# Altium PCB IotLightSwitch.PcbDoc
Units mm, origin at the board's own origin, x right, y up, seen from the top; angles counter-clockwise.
Board outline 68.2 x 35.18 mm, 2 copper layers (Top Layer, Bottom Layer), stack 1.586 mm thick; 15 components, 13 nets, 48 pads, 4 vias.
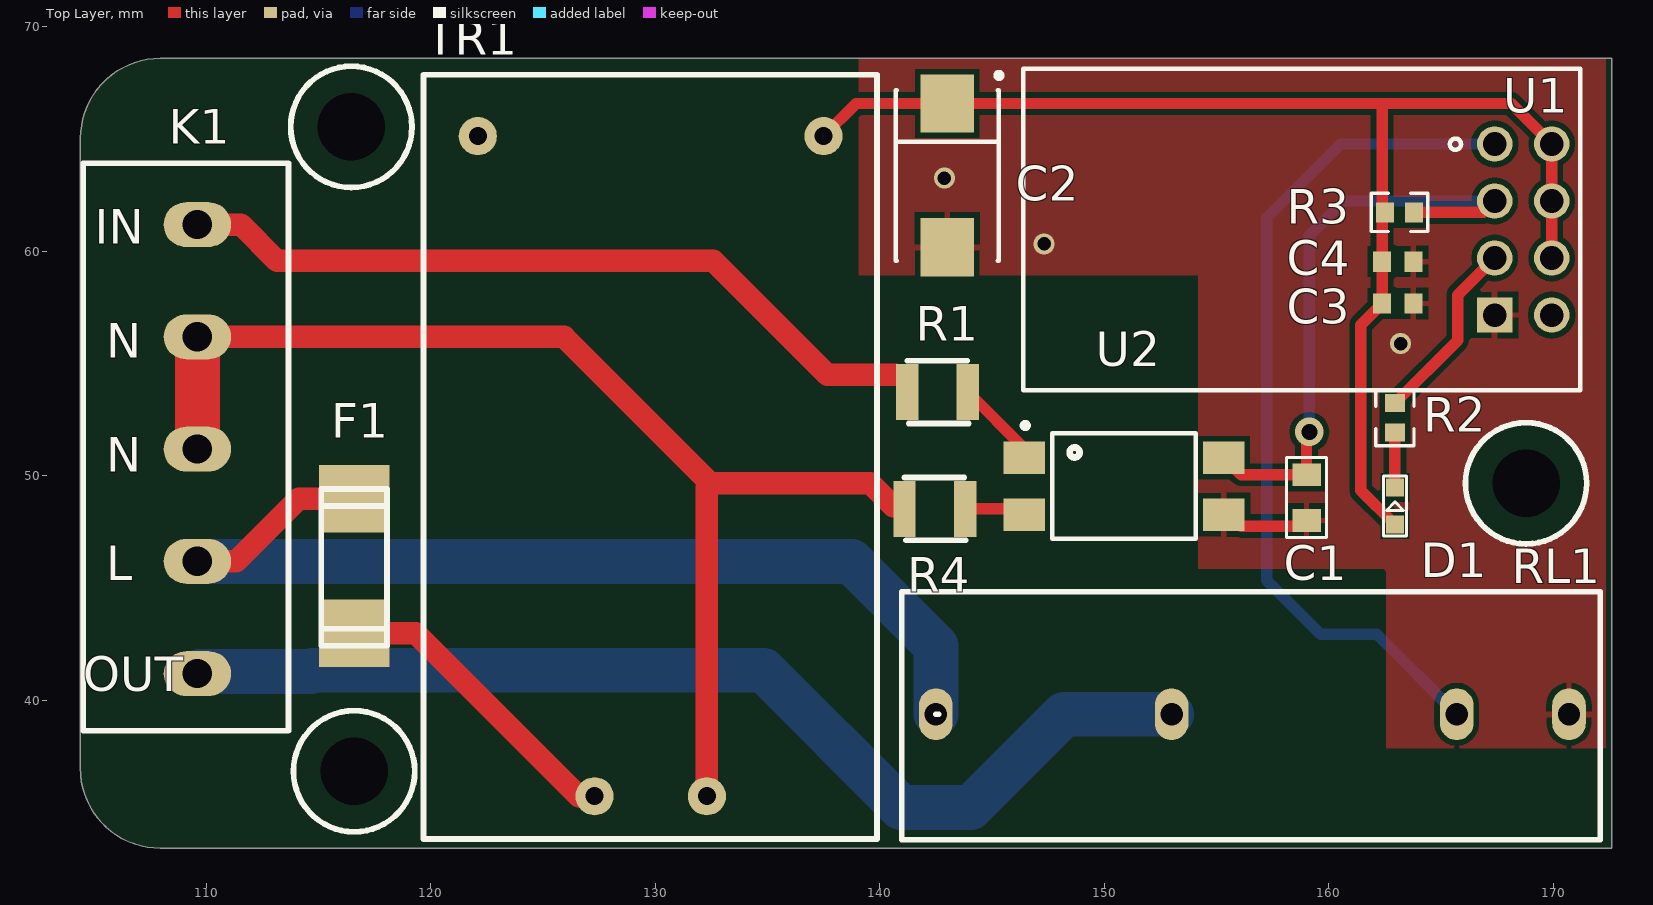
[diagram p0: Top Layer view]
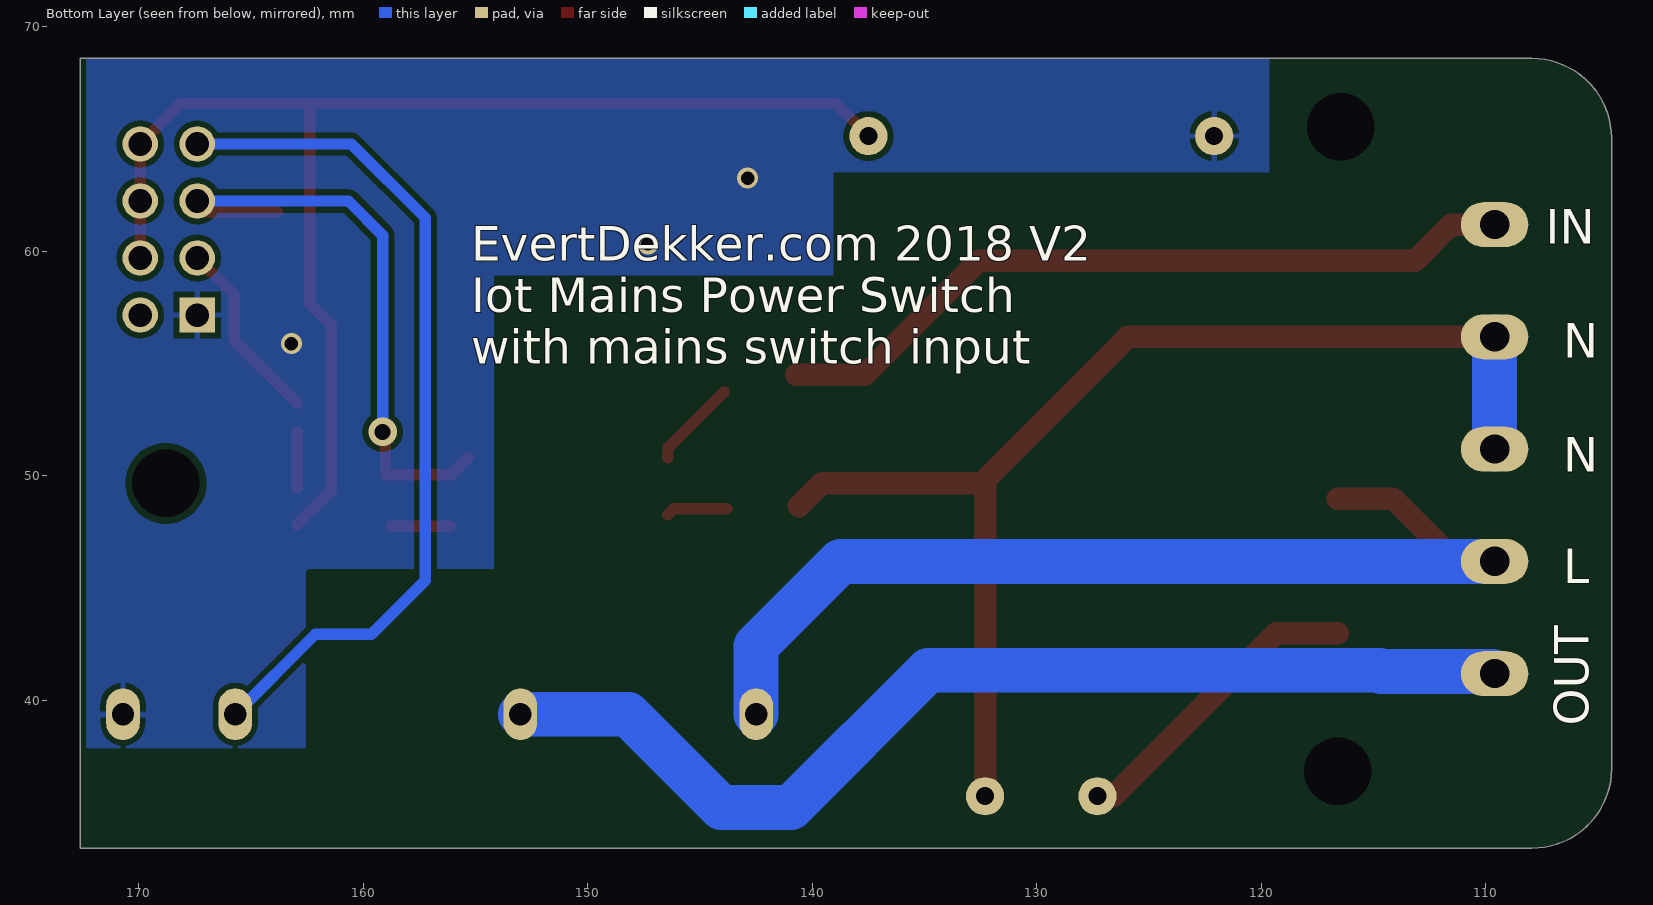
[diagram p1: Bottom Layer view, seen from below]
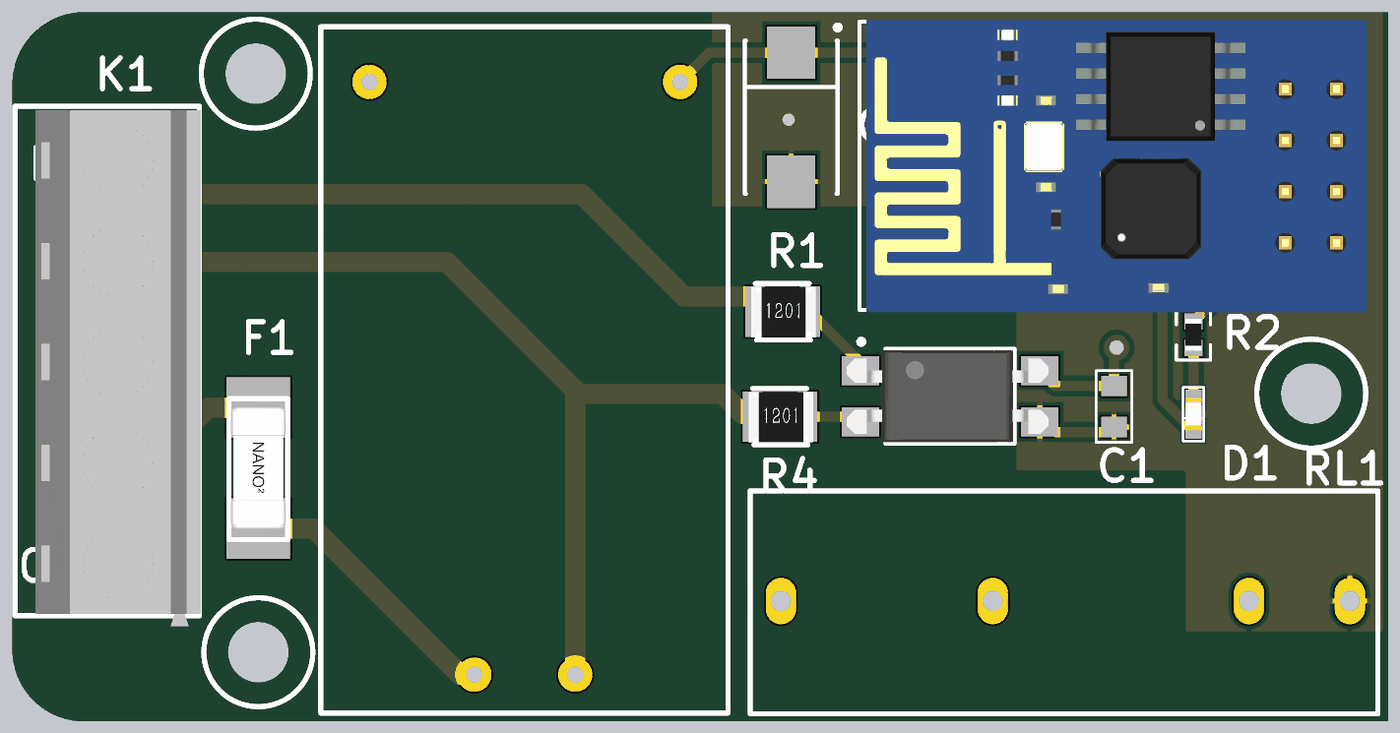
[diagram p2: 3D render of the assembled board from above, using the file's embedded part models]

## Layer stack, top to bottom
Top Solder: solder mask 0.0102, Solder Resist, Dk 3.5
Top Layer: signal copper 0.018
Dielectric1: core 1.55, FR-4, Dk 4.8
Bottom Layer: signal copper 0.018
Bottom Solder: solder mask 0.0102, Solder Resist, Dk 3.5

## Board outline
104.392,36.959 ccw(c107.95,36.959) 107.95,33.401 172.593,33.401 172.593,68.58 107.95,68.58 107.952,68.582 ccw(c107.952,65.024) 104.394,65.024

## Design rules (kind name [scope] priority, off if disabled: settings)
Clearance "Schematic Clearance Constraint" [InNetClass('Undefined')] p1: gap=2
Clearance [All] p2: gap=0.254
PolygonConnect PolygonConnect_1 [IsVia AND InNet('GND')] p1: connectstyle=Direct reliefconductorwidth=0.254 reliefentries=4 polygonreliefangle="90 Angle" airgapwidth=0.254
PolygonConnect [All] p2: connectstyle=Relief reliefconductorwidth=0.254 reliefentries=4 polygonreliefangle="90 Angle" airgapwidth=0.254
RoutingVias [All] p1: holewidth=0.711 width=1.27 viastyle="Through Hole" minholewidth=0.711 minwidth=1.27 maxholewidth=0.711 maxwidth=1.27
SolderMaskExpansion [All] p1: expansion=0.102
Width "Schematic Width Constraint" [InNetClass('Undefined')] p1: maxlimit=3 minlimit=1 preferedwidth=2 minimp=50.000000 maximp=50.000000 favimp=50.000000
Width [All] p2: maxlimit=0.508 minlimit=0.254 preferedwidth=0.305 minimp=50.000000 maximp=50.000000 favimp=50.000000
30 further rules are at their usual default settings.

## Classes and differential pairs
net class Undefined: IN L N NetF1_2 OUT

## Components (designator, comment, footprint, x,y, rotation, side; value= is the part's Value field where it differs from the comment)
C1 "10uF" 0805C-GENERIC 159.004,49.784 r270 top
C2 "T491X" X 143.002,63.373 r270 top
C3 "Cap Semi" 1608[0603] 163.068,57.658 r180 top
C4 "Cap Semi" 1608[0603] 163.068,59.527 r180 top
D1 "Led" LED1608 162.941,48.641 r90 top
F1 "Fuse" SmdFuse1808 116.586,45.974 r270 top
K1 "ScrewTerminal5x5.00mm" ScrewTerminal5x5.00 109.601,51.181 r90 top
R1 "Resistor" RES1210 141.224,53.721 r0 top
R2 "Resistor" RES0603R 162.941,52.578 r90 top
R3 "Resistor" RES0603R 163.144,61.722 r0 top
R4 "Resistor" RES1210 141.097,48.514 r0 top
RL1 "SSR-SAI4002D" SAI4002D 142.494,39.37 r0 top
TR1 "HLK-PM03" HLK-PM03 129.794,50.419 r90 top
U1 "ESP8266-01/ESP-01" XCVR_ESP8266-01/ESP-01 167.386,60.96 r180 top
U2 "SFH6286-3T" SOIC254P977X460-4N 150.876,49.53 r0 top

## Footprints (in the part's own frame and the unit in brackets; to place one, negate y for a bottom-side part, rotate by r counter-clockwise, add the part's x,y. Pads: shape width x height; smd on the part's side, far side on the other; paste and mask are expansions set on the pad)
0805C-GENERIC [mil] "CAPACITOR 0805"
  rect 40x50 smd: 1(-10,0) 2(70,0)
  silkscreen extent -40,-35 100,35, body extent -11,-25 70,25, height 26
1608[0603] [mm] "Chip Capacitor, Body 1.6x0.8mm, IPC High Density"
  rect 0.8x0.9 smd: 1(-0.7,0) 2(0.7,0)
  body extent -0.87,-0.48 0.87,0.48, height 1.3
HLK-PM03 [mm] "Hi-Link HLK-PM03 Power Module"
  round 1.7 hole 0.8: 1(-14.7,2.5) 2(-14.7,-2.5) 3(14.7,7.7) 4(14.7,-7.7)
  silkscreen extent -16.6,-10.08 17.43,10.12, body extent -16.6,-10.07 17.43,10.12, height 15
LED1608 [mm] "1608"
  rect 0.8x0.8 smd: A(-0.826,0) K(0.826,0)
  silkscreen extent -1.33,-0.51 1.33,0.51, body extent -0.8,-0.4 0.8,0.4, height 1.11
RES0603R [mm] "resistor 0603 reflow soldering"
  rect 0.8x0.9 smd: 1(-0.65,0) 2(0.65,0)
  silkscreen extent -1.25,-0.85 1.25,0.85, body extent -0.8,-0.4 0.8,0.4, height 0.45
RES1210 [mm] "RES1210"
  rect 1x2.5 smd: 1(0,0) 2(2.7,0)
  silkscreen extent 0,-1.4 2.73,1.4, body extent -0.2,-1.27 3,1.23, height 0.53
SAI4002D [mm] "SAI4002D Solid State Relay"
  oval 1.5x2.3 hole 1: 1(0,0) 2(10.5,0) 3(23.2,0) 4(28.2,0)
  silkscreen extent -1.52,-5.59 29.59,5.46
ScrewTerminal5x5.00 [mm] "Screw terminal 5p 5.00mm"
  oval 2x3 hole 1.3: 1(-10,0) 2(-5,0) 3(0,0) 4(5,0) 5(10,0)
  silkscreen extent -12.54,-4.06 12.73,5.08, body extent -13.05,-4.14 12.55,4.06, height 10
SmdFuse1808 [mm] "Smd Fuse 1808 Hand Solder"
  rect 3x3.15 smd: 1(-3,0) 2(3,0)
  silkscreen extent -3.43,-1.46 3.56,1.46, body extent -3.05,-1.35 3.05,1.35, height 2.7
SOIC254P977X460-4N [mm]
  rect 1.85x1.45 smd: 1(-4.45,1.27) 2(-4.45,-1.27) 3(4.45,-1.27) 4(4.45,1.27)
  silkscreen extent -4.5,-2.35 3.2,2.8, body extent -5.13,-2.29 4.87,2.29, height 3.86
X [mm] "Capacitor, SM Tantalum; Body 7.3 x 4.3 mm (LxW typ)"
  rect 2.6x2.4 smd: 1(-3.2,0) 2(3.2,0)
  silkscreen extent -4.57,-2.3 3.8,2.43
XCVR_ESP8266-01/ESP-01 [mm]
  rect 1.575x1.575 hole 1.05: 1(0,3.81)
  round 1.575 hole 1.05: 2(-2.54,3.81) 3(0,1.27) 4(-2.54,1.27) 5(0,-1.27) 6(-2.54,-1.27) 7(0,-3.81) 8(-2.54,-3.81)
  silkscreen extent -3.81,-7.15 21,7.15, body extent -4.14,-7.24 20.65,7.26, height 5.88

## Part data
C1: library part 0805C-10UF-16V-X5R-TDK, "CAPACITOR 0805 CERAMIC"
C2: "Solid Tantalum Chip Capacitor, Standard T491 Series - Industrial Grade"
C3 C4: "Capacitor (Semiconductor SIM Model)"
TR1: "Hi-Link HLK-PM03 3.3VDC/3W Power Module"
U2: "SFH6286 Series 5300 Vrms 55 V Phototransistor Output Optocoupler - SMD-4"

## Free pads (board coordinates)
  oval 1.5x2.3 hole 3 unplated: 0(116.459,65.532) 0(116.586,36.83) 0(168.783,49.657)

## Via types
v1: diameter 0.935, hole 0.6, Top Layer to Bottom Layer, 3 vias
v2: diameter 1.27, hole 0.711, Top Layer to Bottom Layer, 1 vias

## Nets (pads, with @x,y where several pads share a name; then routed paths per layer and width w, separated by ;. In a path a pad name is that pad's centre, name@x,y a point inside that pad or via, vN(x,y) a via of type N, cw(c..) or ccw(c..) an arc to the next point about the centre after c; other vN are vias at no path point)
GND: C1.2 C2.2 C3.1 C4.1 RL1.4 TR1.3 U1.1 U2.3 | length 2.7
  Top Layer w0.508: U2.3@156.084,47.752 C1.2@158.75,47.752
  other v1: 163.195,55.88 147.32,60.325 142.875,63.246
IN: K1.5 R1.1 | length 33.9
  Top Layer w1: K1.5 111.539,61.181 113.157,59.563 132.588,59.563 137.668,54.483 140.716,54.483
L: F1.1 K1.2 RL1.1 | length 45.6
  Top Layer w1: K1.2 111.332,46.181 114.125,48.974 F1.1
  Bottom Layer w2: K1.2 138.731,46.181 142.494,42.418 RL1.1
N: K1.3 K1.4 R4.1 TR1.2 | length 57.9
  Top Layer w1: K1.4 125.937,56.181 132.461,49.657 139.573,49.657 140.589,48.641 ; TR1.2 132.294,49.49
  Top Layer w2: K1.3 K1.4
  Bottom Layer w2: K1.3 K1.4
NetC1_1: C1.1 R3.2 U1.5 U2.4 | length 27.4
  Top Layer w0.508: U2.4 156.088,50.038 C1.1 159.004,51.816 v2(159.131,51.943) ; R3.2 166.878,61.722 U1.5
  Bottom Layer w0.508: v2(159.131,51.943) 159.131,60.706 160.655,62.23 U1.5
NetD1_2: D1.K R2.1 | length 2.5
  Top Layer w0.508: D1.K R2.1
NetF1_2: F1.2 TR1.1 | length 13.7
  Top Layer w1: F1.2 119.332,42.974 126.587,35.719 TR1.1
NetR1_2: R1.2 U2.1 | length 4
  Top Layer w0.508: R1.2 146.426,51.219 U2.1
NetR2_2: R2.2 U1.3 | length 8.3
  Top Layer w0.508: R2.2 165.735,56.022 165.735,58.039 U1.3
NetR4_2: R4.2 U2.2 | length 2.7
  Top Layer w0.508: R4.2 146.172,48.514 U2.2
NetRL1_+: RL1.3 U1.7 | length 38.6
  Bottom Layer w0.508: RL1.3 162.138,42.926 159.639,42.926 157.226,45.339 157.226,61.468 160.528,64.77 U1.7
OUT: K1.1 RL1.2 | length 47.7
  Bottom Layer w2: K1.1 109.695,41.275 114.667,41.275 114.722,41.33 134.831,41.33 140.941,35.22 144.047,35.22 148.197,39.37 RL1.2
VCC3V3: C2.1 C3.2 C4.2 D1.A R3.1 TR1.4 U1.4 U1.6 U1.8 | length 58.6
  Top Layer w0.508: TR1.4 138.948,66.573 C2.1 168.123,66.573 U1.8 U1.6 U1.4 ; 162.368,66.511 C4.2 C3.2 161.417,56.707 161.417,49.34 D1.A
pads on no net: U1.2

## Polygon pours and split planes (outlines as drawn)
GND on Bottom Layer "Bottom Layer-No Net" (solid, pour order 2): 119.634,68.58 135.128,68.58 172.339,68.58 172.339,37.719 172.593,37.465 172.212,37.846 162.56,37.846 162.56,45.72 162.433,45.847 154.178,45.847 154.178,58.928 139.065,58.928 139.065,63.5 119.634,63.5
GND on Top Layer "Bottom Layer-No Net" (solid, pour order 0): 139.065,68.58 172.339,68.58 172.339,37.719 172.593,37.465 172.212,37.846 162.56,37.846 162.56,45.72 162.433,45.847 154.178,45.847 154.178,58.928 139.065,58.928 139.065,63.5

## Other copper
Top Layer:
  pour cut-out: 166.116,49.657 ccw(c168.783,49.657) 168.783,46.99 ccw(c168.783,49.657) 171.45,49.657 ccw(c168.783,49.657) 168.783,52.324 ccw(c168.783,49.657)
  pour cut-out: 167.115,49.657 ccw(c168.783,49.657) 168.783,47.989 ccw(c168.783,49.657) 170.451,49.657 ccw(c168.783,49.657) 168.783,51.325 ccw(c168.783,49.657)
Bottom Layer:
  pour cut-out: 166.989,49.657 ccw(c168.783,49.657) 168.783,47.863 ccw(c168.783,49.657) 170.577,49.657 ccw(c168.783,49.657) 168.783,51.451 ccw(c168.783,49.657)

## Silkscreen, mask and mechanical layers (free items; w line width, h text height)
Top Overlay:
  circle w0.254: c168.783,49.657 r2.7
  circle w0.254: c116.586,36.83 r2.7
  circle w0.254: c116.459,65.532 r2.7
  text "IN" at 105.029,60.325 h1.52
  text "N" at 105.537,55.245 h1.52
  text "N" at 105.537,50.165 h1.52
  text "L" at 105.537,45.339 h1.52
  text "OUT" at 104.521,40.386 h1.52
Bottom Overlay:
  text "IN" at 107.315,60.325 h1.52
  text "N" at 106.553,55.245 h1.52
  text "EvertDekker.com 2018 V2 / Iot Mains Power Switch / with mains switch input" at 155.194,54.991 h1.52
  text "N" at 106.553,50.165 h1.52
  text "L" at 106.553,45.212 h1.52
  text "OUT" at 105.41,38.862 h1.52 r270
BoardOutline:
  lines w0.254: 104.392,36.959 ccw(c107.95,36.959) 107.95,33.401 172.593,33.401 172.593,68.58 107.95,68.58 ; 104.394,36.957 104.394,65.024 cw(c107.952,65.024) 107.952,68.582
